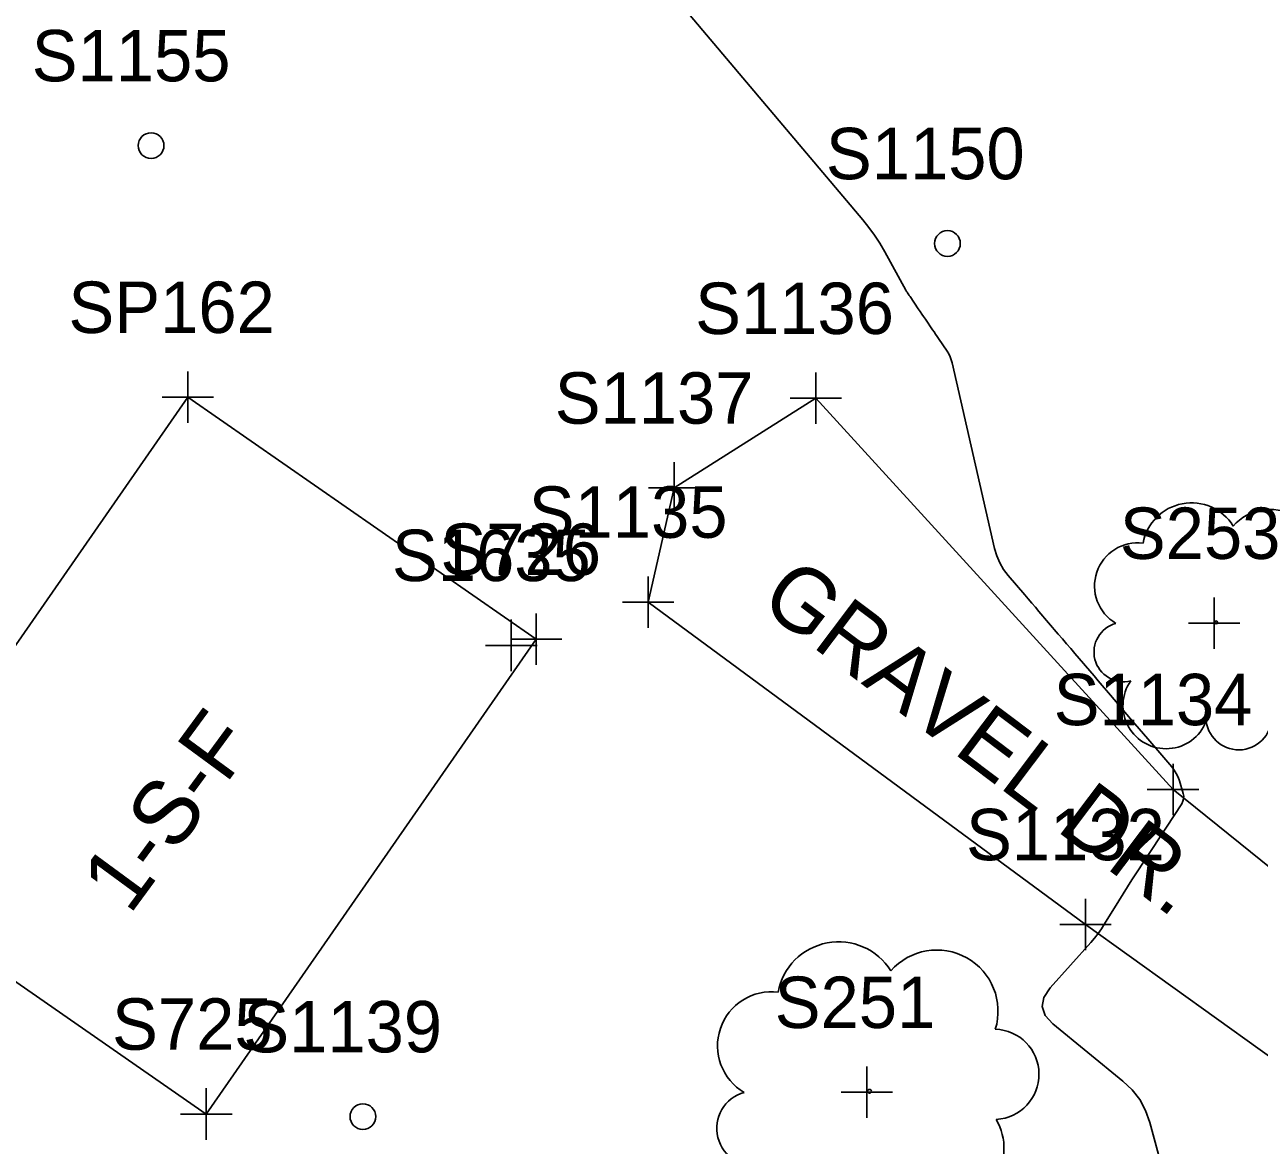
# Model space of a CAD drawing. Extents: x 816928 to 825690, y 436959 to 448212.
# Drawn here: x 818995.2 to 819091.2, y 445399.6 to 445486.8 of the extents above; entities that cross this region are included whole.
import ezdxf

# ---------------------------------------------------------------- set-up
doc = ezdxf.new("R2010")
doc.units = 0
for name, color, linetype in [('SURVEY - CONTOURS - Intermediate with optional Text', 7, 'Continuous'), ('SURVEY - DTM - Spot Points - Locators', 7, 'Continuous'), ('SURVEY - DTM - Spot Points - Point Numbers', 7, 'Continuous'), ('SURVEY - NON-TRANSPORTATION - Buildings', 7, 'Continuous'), ('SURVEY - NON-TRANSPORTATION - Buildings - Points - Locators', 7, 'Continuous'), ('SURVEY - NON-TRANSPORTATION - Buildings - Points - Numbers', 7, 'Continuous'), ('SURVEY - NON-TRANSPORTATION - Buildings Text', 7, 'Continuous'), ('SURVEY - NON-TRANSPORTATION - Features - Points - Locators', 7, 'Continuous'), ('SURVEY - NON-TRANSPORTATION - Features - Points - Numbers', 7, 'Continuous'), ('SURVEY - TRANSPORTATION - Features', 7, 'Continuous'), ('SURVEY - TRANSPORTATION - Features - Points - Locators', 7, 'Continuous'), ('SURVEY - TRANSPORTATION - Features - Points - Numbers', 7, 'Continuous'), ('SURVEY - TRANSPORTATION - Features Text', 7, 'Continuous'), ('SURVEY - VEGETATION - Features - Points - Locators', 7, 'Continuous'), ('SURVEY - VEGETATION - Features - Points - Numbers', 7, 'Continuous'), ('SURVEY - VEGETATION - Features with Text', 7, 'Continuous')]:
    doc.layers.add(name, color=color, linetype=linetype)

msp = doc.modelspace()

# ---------------------------------------------------------------- linework, layer by layer
at = {"layer": 'SURVEY - CONTOURS - Intermediate with optional Text'}
msp.add_lwpolyline([(819031.946, 445505.277), (819060.376, 445471.63), (819060.849, 445471.041), (819061.292, 445470.429), (819061.703, 445469.797), (819062.082, 445469.143), (819063.725, 445466.143), (819063.754, 445466.092), (819063.784, 445466.041), (819063.815, 445465.992), (819063.847, 445465.943), (819063.955, 445465.784), (819063.979, 445465.75), (819064.002, 445465.716), (819064.025, 445465.682), (819064.048, 445465.648), (819064.691, 445464.702), (819064.829, 445464.499), (819064.967, 445464.296), (819065.105, 445464.093), (819065.243, 445463.89), (819065.796, 445463.077), (819065.915, 445462.902), (819066.033, 445462.728), (819066.152, 445462.554), (819066.271, 445462.379), (819066.933, 445461.405), (819067.064, 445461.192), (819067.174, 445460.969), (819067.263, 445460.737), (819067.33, 445460.495), (819070.63, 445446.057), (819070.798, 445445.482), (819071.03, 445444.94), (819071.327, 445444.43), (819071.689, 445443.953), (819072.976, 445442.447), (819073.251, 445442.124), (819073.527, 445441.801), (819073.803, 445441.478), (819074.079, 445441.156), (819075.584, 445439.394), (819075.907, 445439.016), (819076.23, 445438.639), (819076.552, 445438.261), (819076.875, 445437.884), (819078.37, 445436.134), (819078.691, 445435.759), (819079.011, 445435.384), (819079.331, 445435.009), (819079.652, 445434.634), (819081.208, 445432.813), (819081.542, 445432.422), (819081.875, 445432.032), (819082.209, 445431.642), (819082.542, 445431.252), (819084.416, 445429.059), (819084.607, 445428.811), (819084.769, 445428.548), (819084.903, 445428.269), (819085.008, 445427.974), (819085.304, 445426.987), (819085.345, 445426.779), (819085.339, 445426.577), (819085.287, 445426.382), (819085.189, 445426.194), (819081.664, 445420.811), (819081.313, 445420.271), (819080.965, 445419.728), (819080.622, 445419.183), (819080.283, 445418.635), (819079.182, 445416.841), (819078.938, 445416.463), (819078.678, 445416.096), (819078.401, 445415.742), (819078.109, 445415.4), (819074.954, 445411.869), (819074.46, 445411.127), (819074.332, 445410.413), (819074.57, 445409.728), (819075.173, 445409.072), (819080.616, 445404.622), (819081.333, 445403.943), (819081.92, 445403.179), (819082.378, 445402.332), (819082.708, 445401.401), (819083.729, 445397.655)], dxfattribs=at)
at = {"layer": 'SURVEY - DTM - Spot Points - Locators'}
for centre in [(819005.001, 445477.399), (819066.963, 445469.783), (819021.479, 445401.85)]:
    msp.add_circle(centre, 1, dxfattribs=at)
at = {"layer": 'SURVEY - NON-TRANSPORTATION - Buildings'}
msp.add_lwpolyline([(819009.299, 445402.053), (819034.96, 445438.994), (819007.857, 445457.821), (818982.196, 445420.88), (819009.299, 445402.053)], dxfattribs=at)
at = {"layer": 'SURVEY - NON-TRANSPORTATION - Buildings - Points - Locators'}
for p, q in [((819007.857, 445459.821), (819007.857, 445455.821)), ((819009.857, 445457.821), (819005.857, 445457.821)), ((819034.96, 445440.994), (819034.96, 445436.994)), ((819036.96, 445438.994), (819032.96, 445438.994)), ((819009.299, 445404.053), (819009.299, 445400.053)), ((819011.299, 445402.053), (819007.299, 445402.053))]:
    msp.add_line(p, q, dxfattribs=at)
at = {"layer": 'SURVEY - NON-TRANSPORTATION - Features - Points - Locators'}
for p, q in [((819033.028, 445440.518), (819033.028, 445436.518)), ((819035.028, 445438.518), (819031.028, 445438.518))]:
    msp.add_line(p, q, dxfattribs=at)
at = {"layer": 'SURVEY - TRANSPORTATION - Features'}
for points in [[(819121.554, 445405.003), (819110.34, 445406.504), (819084.511, 445427.305), (819056.728, 445457.742), (819045.694, 445450.765), (819043.671, 445441.885)], [(819108.813, 445386.861), (819105.989, 445393.75), (819101.472, 445399.742), (819077.697, 445416.799), (819043.671, 445441.885)]]:
    msp.add_lwpolyline(points, dxfattribs=at)
at = {"layer": 'SURVEY - TRANSPORTATION - Features - Points - Locators'}
for p, q in [((819056.728, 445459.742), (819056.728, 445455.742)), ((819058.728, 445457.742), (819054.728, 445457.742)), ((819045.694, 445452.765), (819045.694, 445448.765)), ((819047.694, 445450.765), (819043.694, 445450.765)), ((819043.671, 445443.885), (819043.671, 445439.885)), ((819045.671, 445441.885), (819041.671, 445441.885)), ((819084.511, 445429.305), (819084.511, 445425.305)), ((819086.511, 445427.305), (819082.511, 445427.305)), ((819077.697, 445418.799), (819077.697, 445414.799)), ((819079.697, 445416.799), (819075.697, 445416.799))]:
    msp.add_line(p, q, dxfattribs=at)
at = {"layer": 'SURVEY - VEGETATION - Features - Points - Locators'}
for p, q in [((819087.707, 445442.241), (819087.707, 445438.241)), ((819089.707, 445440.241), (819085.707, 445440.241)), ((819060.698, 445405.746), (819060.698, 445401.746)), ((819062.698, 445403.746), (819058.698, 445403.746))]:
    msp.add_line(p, q, dxfattribs=at)
at = {"layer": 'SURVEY - VEGETATION - Features with Text'}
for centre, radius in [((819087.864, 445440.303), 0.117), ((819060.895, 445403.822), 0.147)]:
    msp.add_circle(centre, radius, dxfattribs=at)
for centre, radius, start, end in [((819085.945, 445445.772), 3.833, 31.96825, 169.49248), ((819092.058, 445445.288), 3.808, 342.86408, 138.70256), ((819081.769, 445443.132), 3.364, 82.91551, 239.70443), ((819080.671, 445437.997), 2.309, 105.03166, 283.77731), ((819083.973, 445433.831), 3.357, 145.05235, 338.47204), ((819089.628, 445432.94), 2.555, 187.67102, 4.99016), ((819058.495, 445410.658), 4.792, 31.96825, 169.49248), ((819066.137, 445410.054), 4.76, 342.86408, 138.70256), ((819053.276, 445407.359), 4.205, 82.91551, 239.70443), ((819070.571, 445405.142), 3.511, 273.11698, 88.11726), ((819051.903, 445400.94), 2.887, 105.03166, 283.77731), ((819066.835, 445399.388), 4.525, 262.95807, 29.80374)]:
    msp.add_arc(centre, radius, start, end, dxfattribs=at)

# ---------------------------------------------------------------- texts
at = {"layer": 'SURVEY - DTM - Spot Points - Point Numbers'}
for s, p in [('S1155', (818995.714, 445482.399)), ('S1150', (819057.502, 445474.783)), ('S1139', (819012.175, 445406.85))]:
    msp.add_text(s, height=4, dxfattribs=at).set_placement(p)
at = {"layer": 'SURVEY - NON-TRANSPORTATION - Buildings - Points - Numbers'}
for s, p in [('SP162', (818998.569, 445462.821)), ('S726', (819027.514, 445443.994)), ('S725', (819001.963, 445407.053))]:
    msp.add_text(s, height=4, dxfattribs=at).set_placement(p)
at = {"layer": 'SURVEY - NON-TRANSPORTATION - Buildings Text'}
msp.add_text('1-S-F', height=5, rotation=53.6955, dxfattribs=at).set_placement((819003.329, 445417.471))
at = {"layer": 'SURVEY - NON-TRANSPORTATION - Features - Points - Numbers'}
msp.add_text('S1635', height=4, dxfattribs=at).set_placement((819023.74, 445443.518))
at = {"layer": 'SURVEY - TRANSPORTATION - Features - Points - Numbers'}
for s, p in [('S1136', (819047.33, 445462.742)), ('S1137', (819036.406, 445455.765)), ('S1135', (819034.383, 445446.885)), ('S1134', (819075.223, 445432.305)), ('S1132', (819068.409, 445421.799))]:
    msp.add_text(s, height=4, dxfattribs=at).set_placement(p)
at = {"layer": 'SURVEY - TRANSPORTATION - Features Text'}
msp.add_text('GRAVEL DR.', height=5, rotation=323.00006, dxfattribs=at).set_placement((819052.177, 445441.613))
at = {"layer": 'SURVEY - VEGETATION - Features - Points - Numbers'}
for s, p in [('S253', (819080.371, 445445.241)), ('S251', (819053.519, 445408.746))]:
    msp.add_text(s, height=4, dxfattribs=at).set_placement(p)

doc.saveas('drawing.dxf')
